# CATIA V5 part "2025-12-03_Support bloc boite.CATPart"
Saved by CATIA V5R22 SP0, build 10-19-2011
Part number: Support bloc boite
Bounding box of the stored display mesh (mm): x -140 to 140, y -350 to 290, z 0 to 5
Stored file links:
  D:\PER\CAO_PER_MODIF_2025\CAO_PER_pick&place_2024P\Sous_Ensemble_Boite\2025-12-03_Support bloc boite.CATPart
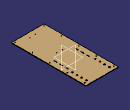
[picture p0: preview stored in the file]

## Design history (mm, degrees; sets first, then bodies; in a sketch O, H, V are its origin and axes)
Body1 (main body)
  Sketch1 on xy-plane, origin (0, 0, 0), H (1, 0, 0), V (0, 1, 0)
    line L1 (140, 350) -> (140, -350)
    line L2 (140, -350) -> (-140, -350)
    line L3 (-140, -350) -> (-140, 350)
    line L4 (-140, 350) -> (140, 350)
    length L1 = 700
    length L4 = 280
    vertical: L1 V, L3 V
    horizontal: L2 H, L4 H
    equidistance: L1 L3 O, L2 L4 O
  Pad1: profile Sketch1, direction (0, 0, 1), length 5
  Sketch2 on end face of Pad1, origin (0, 0, 5), H (1, 0, 0), V (0, 1, 0)
    projected line E1 (140, 350) -> (-140, 350) from edge [face of Pad1 from Sketch1.L4 | end face of Pad1]
    line L1 (140, 350) -> (140, 290)
    line L2 (140, 290) -> (-140, 290)
    line L3 (-140, 290) -> (-140, 350)
    distance L2 E1 = 60
    vertical: L1 V, L3 V
    horizontal: L2 H
  Pocket1: profile Sketch2, direction (0, 0, -1), through (limit type 3)
  DatumCurve1 to DatumCurve12
  Sketch3 on end face of Pad1, origin (0, 0, 5), H (1, 0, 0), V (0, 1, 0)
    projected circle E1 centre (99, 132.4085) radius 3.25 from edge of DatumCurve1
    projected circle E2 centre (99, 172.4085) radius 3.25 from edge of DatumCurve2
    projected circle E3 centre (99, 212.4085) radius 3.25 from edge of DatumCurve3
    projected circle E4 centre (99, 252.4085) radius 3.25 from edge of DatumCurve4
    projected circle E5 centre (-99, 252.4085) radius 3.25 from edge of DatumCurve5
    projected circle E6 centre (-99, 212.4085) radius 3.25 from edge of DatumCurve6
    projected circle E7 centre (-99, 172.4085) radius 3.25 from edge of DatumCurve7
    projected circle E8 centre (-99, 132.4085) radius 3.25 from edge of DatumCurve8
    projected circle E9 centre (22.5, -77.9975) radius 2.5 from edge of DatumCurve9
    projected circle E10 centre (-24.5, -77.9975) radius 2.5 from edge of DatumCurve10
    projected circle E11 centre (23, -308.9975) radius 2.5 from edge of DatumCurve11
    projected circle E12 centre (-24, -308.9975) radius 2.5 from edge of DatumCurve12
  Pocket2: profile Sketch3, direction (0, 0, -1), through (limit type 3)
  Sketch4 on end face of Pad1, origin (0, 0, 5), H (1, 0, 0), V (0, 1, 0)
    circle A1 centre (125, -335) radius 3.5
    point P1 (125, -335)
    reference projected line E1 (-140, -350) -> (140, -350) from edge [face of Pad1 from Sketch1.L2 | end face of Pad1]
    reference projected line E2 (140, -350) -> (140, 350) from edge [face of Pad1 from Sketch1.L1 | end face of Pad1]
    reference intersected line E3 through (0, 0) direction (0, 1) from yz-plane
    circle A2 centre (-125, -335) radius 3.5
    distance P1 E1 = 15
    radius A1 = 3.5
    distance E2 P1 = 15
    symmetry: A1 A2 E3
  Pocket3: profile Sketch4, direction (0, 0, -1), through (limit type 3)
  RectPattern1: of Pocket3, direction 1 instances 5, spacing 150, along edge [face of Pad1 from Sketch1.L1 | end face of Pad1]
  Chamfer1: length 3.7, angle 45, on edge [end face of Pad1 | face of Pocket2 from Sketch3.E8]; edge [end face of Pad1 | face of Pocket2 from Sketch3.E7]; edge [end face of Pad1 | face of Pocket2 from Sketch3.E6]; edge [end face of Pad1 | face of Pocket2 from Sketch3.E5]
  Chamfer2: length 3.7, angle 45, on edge [end face of Pad1 | face of Pocket2 from Sketch3.E1]; edge [end face of Pad1 | face of Pocket2 from Sketch3.E2]; edge [end face of Pad1 | face of Pocket2 from Sketch3.E3]; edge [end face of Pad1 | face of Pocket2 from Sketch3.E4]
  DatumCurve13 to DatumCurve36
  Sketch5 on start face of Pad1, origin (0, 0, 0), H (1, 0, 0), V (0, -1, 0)
    projected line E1 (89, 6.9975) -> (89, 31.4975) from edge of DatumCurve13
    projected line E2 (94, 6.9975) -> (94, 31.4975) from edge of DatumCurve14
    projected line E3 (89, 6.9975) -> (94, 6.9975) from edge of DatumCurve15
    projected line E4 (89, 31.4975) -> (94, 31.4975) from edge of DatumCurve16
    projected line E5 (89, -41.0025) -> (89, -17.0025) from edge of DatumCurve17
    projected line E6 (94, -41.0025) -> (94, -17.0025) from edge of DatumCurve18
    projected line E7 (89, -41.0025) -> (94, -41.0025) from edge of DatumCurve19
    projected line E8 (89, -17.0025) -> (94, -17.0025) from edge of DatumCurve20
    projected line E9 (89, -89.5025) -> (89, -65.0025) from edge of DatumCurve21
    projected line E10 (94, -89.5025) -> (94, -65.0025) from edge of DatumCurve22
    projected line E11 (89, -89.5025) -> (94, -89.5025) from edge of DatumCurve23
    projected line E12 (89, -65.0025) -> (94, -65.0025) from edge of DatumCurve24
    projected line E13 (-89, -89.5025) -> (-89, -65.0025) from edge of DatumCurve25
    projected line E14 (-94, -65.0025) -> (-89, -65.0025) from edge of DatumCurve26
    projected line E15 (-94, -89.5025) -> (-94, -65.0025) from edge of DatumCurve27
    projected line E16 (-94, -89.5025) -> (-89, -89.5025) from edge of DatumCurve28
    projected line E17 (-89, -41.0025) -> (-89, -17.0025) from edge of DatumCurve29
    projected line E18 (-94, -41.0025) -> (-94, -17.0025) from edge of DatumCurve30
    projected line E19 (-94, -41.0025) -> (-89, -41.0025) from edge of DatumCurve31
    projected line E20 (-94, -17.0025) -> (-89, -17.0025) from edge of DatumCurve32
    projected line E21 (-89, 6.9975) -> (-89, 31.4975) from edge of DatumCurve33
    projected line E22 (-94, 6.9975) -> (-94, 31.4975) from edge of DatumCurve34
    projected line E23 (-94, 6.9975) -> (-89, 6.9975) from edge of DatumCurve35
    projected line E24 (-94, 31.4975) -> (-89, 31.4975) from edge of DatumCurve36
  Pocket4: profile Sketch5, direction (0, 0, 1), through (limit type 3)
